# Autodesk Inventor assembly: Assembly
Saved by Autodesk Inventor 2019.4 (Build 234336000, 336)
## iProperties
Created: 2020-02
Part Number: Assembly
Document SubType Name: Assembly
Designer: Administrator
Title: Assembly v113
Author: Administrator
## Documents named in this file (31)
- c:\worker\convert-fusion-r01\tmp\job-1\5\output\files\e4333473-a38b-4431-9958-ad24a2f67704\bda59de0-16c7-46d3-8c42-5fdd93595069.iam
- c:\worker\convert-fusion-r01\tmp\job-1\5\output\files\e4333473-a38b-4431-9958-ad24a2f67704\4mmBearing v4.iam
- c:\worker\convert-fusion-r01\tmp\job-1\5\output\files\e4333473-a38b-4431-9958-ad24a2f67704\MainShaft.ipt
- c:\worker\convert-fusion-r01\tmp\job-1\5\output\files\e4333473-a38b-4431-9958-ad24a2f67704\4mmBearing v4_1.iam
- c:\worker\convert-fusion-r01\tmp\job-1\5\output\files\e4333473-a38b-4431-9958-ad24a2f67704\6mmBearing v2.ipt
- c:\worker\convert-fusion-r01\tmp\job-1\5\output\files\e4333473-a38b-4431-9958-ad24a2f67704\BrassTube v3.ipt
- c:\worker\convert-fusion-r01\tmp\job-1\5\output\files\e4333473-a38b-4431-9958-ad24a2f67704\Spacer v9.ipt
- c:\worker\convert-fusion-r01\tmp\job-1\5\output\files\e4333473-a38b-4431-9958-ad24a2f67704\Generator_Gear_large(21 teeth) v4.ipt
- c:\worker\convert-fusion-r01\tmp\job-1\5\output\files\e4333473-a38b-4431-9958-ad24a2f67704\Generator v12.iam
- c:\worker\convert-fusion-r01\tmp\job-1\5\output\files\e4333473-a38b-4431-9958-ad24a2f67704\Generator_gear_small(10 teeth) v2.ipt
- c:\worker\convert-fusion-r01\tmp\job-1\5\output\files\e4333473-a38b-4431-9958-ad24a2f67704\Servo v14.ipt
- c:\worker\convert-fusion-r01\tmp\job-1\5\output\files\e4333473-a38b-4431-9958-ad24a2f67704\Rotor_mount v9.ipt
- c:\worker\convert-fusion-r01\tmp\job-1\5\output\files\e4333473-a38b-4431-9958-ad24a2f67704\Blade_mount v18.iam
- c:\worker\convert-fusion-r01\tmp\job-1\5\output\files\e4333473-a38b-4431-9958-ad24a2f67704\Blade_mount v18_1.iam
- c:\worker\convert-fusion-r01\tmp\job-1\5\output\files\e4333473-a38b-4431-9958-ad24a2f67704\Blade_mount v18_2.iam
- c:\worker\convert-fusion-r01\tmp\job-1\5\output\files\e4333473-a38b-4431-9958-ad24a2f67704\Blade v3.ipt
- c:\worker\convert-fusion-r01\tmp\job-1\5\output\files\e4333473-a38b-4431-9958-ad24a2f67704\BallJoint v14.iam
- c:\worker\convert-fusion-r01\tmp\job-1\5\output\files\e4333473-a38b-4431-9958-ad24a2f67704\BallJoint v14_1.iam
- c:\worker\convert-fusion-r01\tmp\job-1\5\output\files\e4333473-a38b-4431-9958-ad24a2f67704\BallJoint v14_2.iam
- c:\worker\convert-fusion-r01\tmp\job-1\5\output\files\e4333473-a38b-4431-9958-ad24a2f67704\BallJoint v14_3.iam
- c:\worker\convert-fusion-r01\tmp\job-1\5\output\files\e4333473-a38b-4431-9958-ad24a2f67704\BallJoint v14_4.iam
- c:\worker\convert-fusion-r01\tmp\job-1\5\output\files\e4333473-a38b-4431-9958-ad24a2f67704\BallJoint v14_5.iam
- c:\worker\convert-fusion-r01\tmp\job-1\5\output\files\e4333473-a38b-4431-9958-ad24a2f67704\Rotor_Bearing_mount v5.ipt
- c:\worker\convert-fusion-r01\tmp\job-1\5\output\files\e4333473-a38b-4431-9958-ad24a2f67704\Blade_Shaft_Retention_Ring v1.ipt
- c:\worker\convert-fusion-r01\tmp\job-1\5\output\files\e4333473-a38b-4431-9958-ad24a2f67704\3mmBearing v2.ipt
- c:\worker\convert-fusion-r01\tmp\job-1\5\output\files\e4333473-a38b-4431-9958-ad24a2f67704\20mmRod v1.ipt
- c:\worker\convert-fusion-r01\tmp\job-1\5\output\files\e4333473-a38b-4431-9958-ad24a2f67704\Swash_Plate_Stationary_Mount v3.ipt
- c:\worker\convert-fusion-r01\tmp\job-1\5\output\files\e4333473-a38b-4431-9958-ad24a2f67704\BallJoint v14_6.iam
- c:\worker\convert-fusion-r01\tmp\job-1\5\output\files\e4333473-a38b-4431-9958-ad24a2f67704\Servo_arm v5.ipt
- c:\worker\convert-fusion-r01\tmp\job-1\5\output\files\e4333473-a38b-4431-9958-ad24a2f67704\Servo_Connector_Rod v1.ipt
- c:\worker\convert-fusion-r01\tmp\job-1\5\output\files\e4333473-a38b-4431-9958-ad24a2f67704\Assembly v113.ipt
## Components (40 placed, 21 different names)
1. 4mmBearing v4:1 [sub-assembly]
2. MainShaft:1
3. 4mmBearing v4:2 [sub-assembly]
4. 6mmBearing v2:1
5. BrassTube v3:1
6. Spacer v9:1
7. Generator_Gear_large(21 teeth) v4:1
8. Generator v12:1 [sub-assembly]
9. Generator_gear_small(10 teeth) v2:1
10. Servo v14:1
11. Rotor_mount v9:1
12. Blade_mount v18:1 [sub-assembly]
13. Blade_mount v18:2 [sub-assembly]
14. Blade_mount v18:3 [sub-assembly]
15. Blade v3:1
16. Blade v3:2
17. Blade v3:3
18. BallJoint v14:1 [sub-assembly]
19. BallJoint v14:2 [sub-assembly]
20. BallJoint v14:3 [sub-assembly]
21. BallJoint v14:4 [sub-assembly]
22. BallJoint v14:5 [sub-assembly]
23. BallJoint v14:6 [sub-assembly]
24. Rotor_Bearing_mount v5:1
25. Rotor_Bearing_mount v5:2
26. Rotor_Bearing_mount v5:3
27. Blade_Shaft_Retention_Ring v1:1
28. Blade_Shaft_Retention_Ring v1:2
29. Blade_Shaft_Retention_Ring v1:3
30. 3mmBearing v2:3
31. 3mmBearing v2:4
32. 3mmBearing v2:5
33. 20mmRod v1:5
34. 20mmRod v1:6
35. 20mmRod v1:7
36. Swash_Plate_Stationary_Mount v3:1
37. BallJoint v14:7 [sub-assembly]
38. Servo_arm v5:1
39. Servo_Connector_Rod v1:1
40. Assembly v113
